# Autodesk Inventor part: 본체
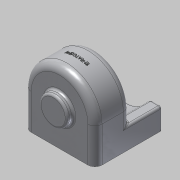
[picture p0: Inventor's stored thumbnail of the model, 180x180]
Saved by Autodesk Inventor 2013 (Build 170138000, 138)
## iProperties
Created: 2015-02
Part Number: 본체
Material: 알루미늄 6061
Document SubType Name: Modeling
Designer: Administrator
Density: 1 g/cm^3
Author: Administrator
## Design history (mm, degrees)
sketch "스케치1"
  geometry: L1 (-50, 0)-(-50, -50); L2 (-50, -50)-(50, -50); L3 (50, -50)-(50, 0); A1 r 50 centre (0, 0) between (50, 0) and (-50, 0); 1 further point
  constraints: 6 end point, 2 point on circle, 2 tangent, 1 centre point, 1 coincident, 1 horizontal alignment, 1 parallel, 1 perpendicular, 1 vertical
  dimensions: "d0" = 100 diameter of A1; "d2" = 50 distance from line of point (0, 0) L2
extrude "돌출1" new body sketch "스케치1" distance "d3" = 50; taper "d4" = 0 deg
feature "쉘1" dims "d5" = 4
sketch "스케치2"
  geometry: L1 (50, 0)-(50, 50) reference; L2 (50, 50)-(-50, 50) reference; L3 (-50, 50)-(-50, 0) reference; L4 (-50, 50)-(50, 50); L5 (50, 50)-(50, 20); L6 (-50, 20)-(-50, 50); L7 (50, 20)-(34.641, 20); L8 (-34.641, 20)-(-50, 20); A1 r 50 centre (0, 0) between (-50, 0) and (50, 0) reference; A2 r 40 centre (0, 0) between (34.641, 20) and (-34.641, 20)
  constraints: 10 end point, 3 collinear, 3 parallel, 2 point on circle, 1 centre point, 1 coincident, 1 horizontal, 1 perpendicular
  dimensions: "d7" = 80 diameter of A2; "d8" = 30 distance between parallel lines of L2 L8; "d9" = 30 distance between parallel lines of L2 L7
extrude "돌출2" join sketch "스케치2" distance "d10" = 45; taper "d11" = 0 deg
sketch "스케치3"
  geometry: C1 r 25 at (0, 0); A1 r 40 centre (0, 0) between (34.641, 20) and (-34.641, 20) reference
  constraints: 1 centre point, 1 coincident
  dimensions: "d12" = 50 diameter of C1
extrude "돌출3" join sketch "스케치3" distance "d15" = 10; taper "d16" = 0 deg
sketch "스케치4" dims "d17" = 36
  geometry: C1 r 25 at (0, 0) reference; C2 r 14 at (0, 0); C3 r 10 at (0, 0); 2 further points
  constraints: 3 coincident, 2 centre point, 2 vertical alignment, 2 other
  dimensions: "d18" = 28 diameter of C2; "d19" = 20 diameter of C3
extrude "돌출4" cut sketch "스케치4" distance "d20" = 10; taper "d21" = 0 deg
extrude "돌출5" cut sketch "스케치4" distance "d22" = 14; taper "d23" = 0 deg
hole "구멍1" sketch "스케치4" diameter "d24" = 2.459; stored, may be unused: countersink angle "d28" = 82 deg, drill point angle "d30" = 118 deg; dims "d25" = 6, "d26" = 3.023, "d27" = 2, "d29" = 9
fillet "모깎기1" dims "d34" = 0.3
chamfer "모따기1" distance "d35" = 1; stored, may be unused: second distance "d36" = 2, angle "d37" = 45 deg
feature "면 기울기1" dims angle "d38" = 20 deg
sketch "스케치5"
  geometry: C1 r 20 at (0, 0); A1 r 50 centre (0, 0) between (50, 0) and (-50, 0) reference
  constraints: 1 centre point, 1 coincident
  dimensions: "d39" = 40 diameter of C1
extrude "돌출6" join sketch "스케치5" distance "d42" = 9; taper "d43" = 0 deg
sketch "스케치6"
  geometry: C1 r 14 at (0, 0); C2 r 10 at (0, 0); A1 r 46 centre (0, 0) between (-46, 0) and (46, 0) reference
  constraints: 2 centre point, 2 coincident
  dimensions: "d44" = 28 diameter of C1; "d45" = 20 diameter of C2
extrude "돌출7" cut sketch "스케치6" distance "d46" = 8; taper "d47" = 0 deg
extrude "돌출8" cut sketch "스케치6" distance "d48" = 10; taper "d49" = 0 deg
fillet "모깎기2" dims "d50" = 3
fillet "모깎기3" dims "d51" = 0.3
chamfer "모따기2" distance "d52" = 1; stored, may be unused: second distance "d53" = 2, angle "d54" = 45 deg
sketch "스케치7"
  geometry: L1 (0, 0)-(100, 0) reference; L2 (0, 95)-(100, 95) reference; L3 (0, 0)-(0, 95) reference; L4 (50, 105.394)-(50, -22.188); 6 further points
  constraints: 2 end point, 1 horizontal alignment, 1 midpoint, 1 parallel, 1 point on line, 1 symmetric about line, 1 vertical alignment
  dimensions: "d55" = 9 distance from line of L2 point (8.25, 86); "d57" = 33 distance of point (8.25, 86) point (8.25, 53); "d58" = 83.5 distance of point (91.75, 86) point (8.25, 86); "d59" = 33 distance of point (91.75, 86) point (91.75, 53)
hole "구멍2" sketch "스케치7" at (8.25, 86), (91.75, 86), (91.75, 53), (8.25, 53) diameter "d60" = 5.134; stored, may be unused: countersink angle "d64" = 82 deg, drill point angle "d66" = 118 deg; dims "d61" = 10, "d62" = 3.023, "d63" = 2, "d65" = 13
fillet "모깎기4" dims "d67" = 10
fillet "모깎기5" dims "d68" = 3
fillet "모깎기6" dims "d69" = 3
fillet "모깎기7" dims "d70" = 6
node "작업 평면1"
sketch "스케치8"
  geometry: L1 (40, 0)-(-40, 0) reference; 2 further points
  constraints: 1 vertical alignment, 1 other
  dimensions: "d74" = 25 distance from line of L1 point (0, 25)
feature "엠보싱1" sketch "스케치8" dims "d0" = 100, "d2" = 50, "d7" = 80, "d8" = 30, "d9" = 30, "d72" = 0.5, "d73" = 0
node "솔리드1"
pattern_circular "원형 패턴1" dims angle "d32" = 360 deg
